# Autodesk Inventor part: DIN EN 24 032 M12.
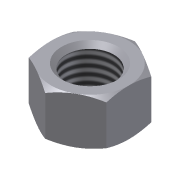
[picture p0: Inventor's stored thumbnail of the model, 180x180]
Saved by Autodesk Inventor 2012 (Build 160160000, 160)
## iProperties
Shininess: 20.0
Length Units: 11269
Angle Units: 11279
Time Units: 11290
Mass Units: 11283
Length Display Precision: 3
Angle Display Precision: 2
Company: CAD-Verlag
Created: 2001-01
Part Number: DIN EN 24 032 M12.
Material: Steel, Mild
Document SubType Name: Modeling
Description: Mutter DIN EN 24 032 M12.
Standard: DIN EN 24 032
Density: 7.86 g/cm^3
Density: 7.86
Volumn: 1.1364084233749536
Area: 9.602775185060906
PropertySet Name: Model Information
Control State: 0
Master: False
Checked Out: False
BOM1: Mutter
BOM2: M12
BOM3: DIN EN 24 032
d64: 0,000 mm
+MSCProtocol1+ProtocolID: P00040924060223925
+MSCProtocol2+Protocol: P00040924060223925<@PID>[Version]<@EL>Version=2.2<@EL>[Data]<@EL>mass=0.014205{kg<@EL>m=10.8{mm<@EL>s=18{mm<@EL>d=12{mm<@EL>P=1.75{mm<@EL>[Files]<@EL>DataFile=S
Author: Jürgen Kronas
Revision Number: 2
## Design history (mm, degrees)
node "WorkPlane8"
node "WorkPlane10"
sketch "Sketch1"
  geometry: 1 further point
node "WorkPoint1"
sketch "Sketch2" dims "d2" = 16.2 (= -0.15 x prf_d + prf_s)
  geometry: C1 r 5 at (0, 0) reference; A1 r 8 centre (0, 0) between (-4, 6.928) and (-8, 0) reference; A2 r 8 centre (0, 0) between (4, 6.928) and (-4, 6.928) reference; A3 r 8 centre (0, 0) between (8, 0) and (4, 6.928) reference; A4 r 8 centre (0, 0) between (4, -6.928) and (8, 0) reference; A5 r 8 centre (0, 0) between (-4, -6.928) and (4, -6.928) reference; A6 r 8 centre (0, 0) between (-8, 0) and (-4, -6.928) reference; 1 further point
extrude "ExtrusionBlind1" new body sketch "Sketch2" distance "d3" = 10.8 (= prf_m); taper "d4" = 0 deg
sketch "Sketch3"
  geometry: 1 further point
node "WorkPoint2"
sketch "Sketch4"
  geometry: L1 (9, -5.196)-(9, 5.196); L2 (0, -10.392)-(9, -5.196); L3 (-9, -5.196)-(0, -10.392); L4 (-9, 5.196)-(-9, -5.196); L5 (0, 10.392)-(-9, 5.196); L6 (9, 5.196)-(0, 10.392); C1 r 9 at (0, 0); C2 r 8.1 at (0, 0) reference
  constraints: 12 end point, 6 tangent, 2 parallel, 2 vertical, 1 centre point, 1 concentric
  dimensions: "d8" = 18 diameter of C1 (= prf_s)
extrude "ExtrusionBlind2" join sketch "Sketch4" distance "d9" = 10.8 (= prf_m); taper "d10" = 0 deg
sketch "Sketch6"
  geometry: L1 (-10.392, -9.996)-(-9, -10.8); L2 (0, -12.96)-(0, 2.16) reference; L3 (-10.392, -9.996)-(-10.392, -10.8); L4 (-10.392, -10.8)-(-9, -10.8); L5 (-10.392, 0)-(-10.392, -10.8) reference
  constraints: 6 end point, 1 parallel, 1 perpendicular
  dimensions: "d32" = 9 distance from line of L2 L1.end (= 0.5 x prf_s); "d34" = 0 distance between parallel lines of L3 L5; "d36" = 0 distance from line of L5.end L4; "d37" = 120 deg angle of L5 L1
revolve "RevolutionFull1" sketch "Sketch6" stored, may be unused: angle "d21" = 360 deg
sketch "Sketch7"
  geometry: L1 (-10.392, 0)-(-10.392, -0.804); L2 (-9, 0)-(-10.392, 0); L3 (-10.392, -0.804)-(-9, 0); L4 (-10.392, 0)-(-10.392, -9.996) reference; L5 (0, -12.96)-(0, 2.16) reference
  constraints: 6 end point, 1 horizontal, 1 vertical
  dimensions: "d38" = 0 distance between parallel lines of L4 L1; "d39" = 0 distance from line of L4.start L2; "d40" = 9 distance from line of L5 L2.start (= d32); "d41" = 120 deg angle of L1 L3
revolve "RevolutionFull2" sketch "Sketch7" stored, may be unused: angle "d26" = 360 deg
sketch "Sketch8"
  geometry: A1 r 9 centre (0, 0) between (9, 0) and (4.5, 7.794) reference; 1 further point
  constraints: 1 coincident
hole "Ms_Hole" sketch "Sketch8" at (0, 0) diameter "d57" = 11.0528; stored, may be unused: countersink angle "d61" = 82 deg, drill point angle "d63" = 118 deg; dims "d58" = 6, "d59" = 4, "d60" = 2, "d62" = 8
node "MSC_PT1"
node "MSC_PT2"
node "MSC_PF1"
node "MSC_A1"
chamfer "Chamfer1" distance "d55" = 1.05 (= 0.6 x prf_p); stored, may be unused: second distance "d56" = 1.05 (= 0.6 x prf_p), angle "d65" = 45 deg
node "Volumenkörper1"
node "Volumenkörpern"
node "Oberflächenkörpern"
other parameters: "prf_d" = 12 [user parameter; used in 1 equation term], "prf_m" = 10.8 [user parameter; used in 3 equation terms], "prf_s" = 18 [user parameter; used in 3 equation terms], "d0" = -10.8 (computed from prf_m), "d1" = 14.5 (derived), "d5" = 0, "d7" = 16 (derived), "d15" = 30 deg (derived), "d17" = 0 (derived), "d18" = 0 (derived), "d19" = 0 (derived), "d20" = 0 (derived), "d22" = 30 deg (derived), "d24" = 0 (derived), "d25" = 0 (derived), "d52" = 0, "d53" = 0, "d54" = 0, "prf_p" = 1.75 [user parameter; used in 2 equation terms], "d64" = 0
